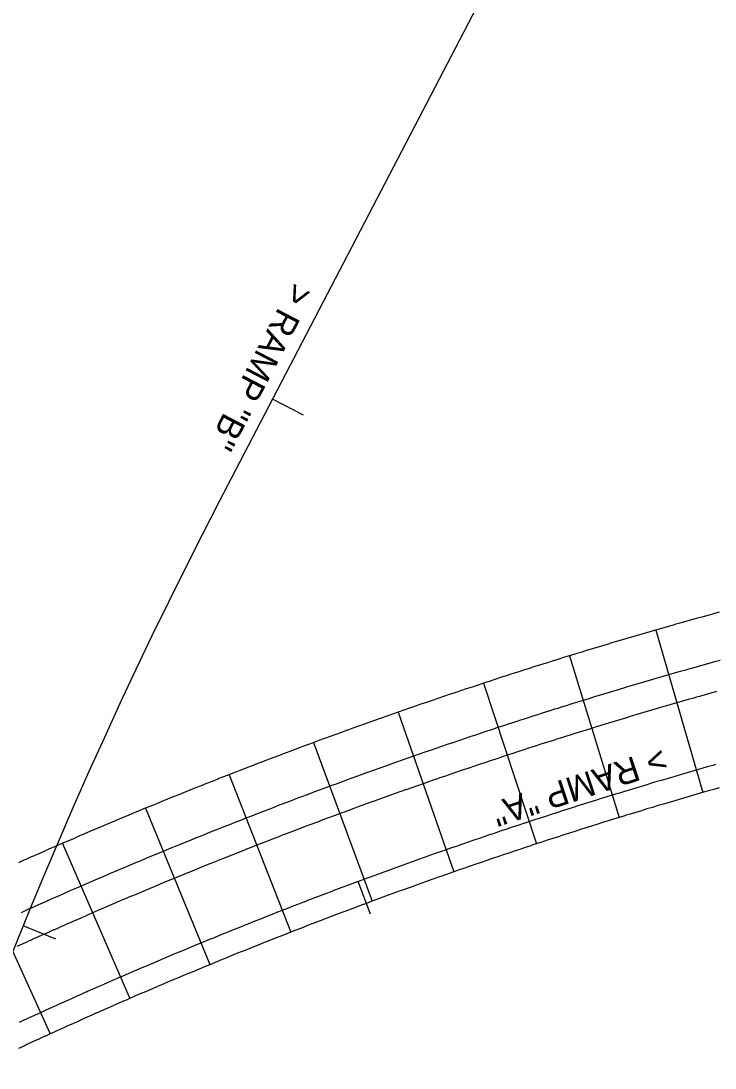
# Model space of a CAD drawing. Extents: x 2145147 to 2158018, y 137519 to 148068.
# Drawn here: x 2150298.8 to 2150417.8, y 143485.8 to 143665.3 of the extents above; entities that cross this region are included whole.
import ezdxf

# ---------------------------------------------------------------- set-up
doc = ezdxf.new("R2010")
doc.units = 0
for name, color, linetype in [('PR_Align_Ramp_A', 7, 'Continuous'), ('PR_Align_Ramp_A_Label', 7, 'Continuous'), ('PR_Align_Ramp_B', 7, 'Continuous'), ('PR_Align_Ramp_B_Label', 7, 'Continuous'), ('PR_Joint_Contraction', 7, 'Continuous'), ('PR_Joint_Long', 7, 'Continuous'), ('PR_Road_Concrete', 7, 'Continuous')]:
    doc.layers.add(name, color=color, linetype=linetype)

msp = doc.modelspace()

# ---------------------------------------------------------------- linework, layer by layer
at = {"layer": 'PR_Align_Ramp_A'}
msp.add_lwpolyline([(2150358.73, 143512.15), (2150356.64, 143517.77)], dxfattribs=at)
at = {"layer": 'PR_Align_Ramp_B'}
msp.add_line((2150377.59, 143669), (2150332.79, 143582.93), dxfattribs=at)
for points in [[(2150347.25, 143597.71), (2150341.93, 143600.48)], [(2150304.74, 143507.88), (2150299.18, 143510.14)]]:
    msp.add_lwpolyline(points, dxfattribs=at)
msp.add_arc((2151085.75, 143191.05), 848.83, 152.5051, 261.84091, dxfattribs=at)
at = {"layer": 'PR_Joint_Contraction'}
for p, q in [((2150407.66, 143560.88), (2150415.7, 143533.02)), ((2150392.85, 143556.46), (2150401.4, 143528.75)), ((2150378.12, 143551.77), (2150387.17, 143524.22)), ((2150363.48, 143546.81), (2150373.04, 143519.43)), ((2150348.93, 143541.58), (2150358.99, 143514.38)), ((2150334.48, 143536.08), (2150345.04, 143509.07)), ((2150320.14, 143530.33), (2150331.19, 143503.51)), ((2150305.9, 143524.31), (2150317.44, 143497.7)), ((2150291.78, 143518.03), (2150303.8, 143491.64))]:
    msp.add_line(p, q, dxfattribs=at)
at = {"layer": 'PR_Joint_Long'}
for points in [[(2150418.69, 143555.69), (2150417.72, 143555.42), (2150416.73, 143555.14), (2150415.74, 143554.86), (2150414.76, 143554.59), (2150413.78, 143554.31), (2150413.28, 143554.17), (2150412.8, 143554.03), (2150411.81, 143553.75), (2150410.83, 143553.47), (2150409.86, 143553.19), (2150408.87, 143552.91), (2150407.91, 143552.63), (2150407.67, 143552.56), (2150406.91, 143552.33), (2150405.93, 143552.05), (2150404.95, 143551.76), (2150403.98, 143551.47), (2150402.99, 143551.18), (2150402.31, 143550.97), (2150402.28, 143550.97), (2150401.04, 143550.59), (2150400.06, 143550.3), (2150399.09, 143550), (2150398.11, 143549.71), (2150397.13, 143549.41), (2150396.44, 143549.2), (2150396.15, 143549.11), (2150395.18, 143548.81), (2150394.21, 143548.51), (2150393.23, 143548.21), (2150392.26, 143547.9), (2150391.27, 143547.59), (2150390.84, 143547.46), (2150390.31, 143547.29), (2150389.33, 143546.98), (2150388.36, 143546.67), (2150387.39, 143546.36), (2150386.42, 143546.05), (2150385.42, 143545.73), (2150385.24, 143545.67), (2150384.47, 143545.43), (2150383.5, 143545.11), (2150382.53, 143544.8), (2150381.56, 143544.48), (2150380.59, 143544.16), (2150379.74, 143543.88), (2150379.66, 143543.85), (2150378.65, 143543.52), (2150377.68, 143543.2), (2150376.72, 143542.88), (2150375.75, 143542.55), (2150374.78, 143542.23), (2150374.14, 143542.01), (2150373.8, 143541.9), (2150372.85, 143541.57), (2150371.88, 143541.25), (2150370.91, 143540.91), (2150369.95, 143540.58), (2150368.98, 143540.25), (2150368.59, 143540.12), (2150368.03, 143539.92), (2150367.05, 143539.58), (2150366.09, 143539.25), (2150365.12, 143538.91), (2150364.17, 143538.57), (2150363.18, 143538.22), (2150363.04, 143538.17), (2150362.24, 143537.89), (2150361.28, 143537.55), (2150360.32, 143537.21), (2150359.36, 143536.86), (2150358.4, 143536.52), (2150357.53, 143536.2), (2150357.4, 143536.16), (2150356.48, 143535.82), (2150355.51, 143535.47), (2150354.56, 143535.12), (2150353.6, 143534.77), (2150352.65, 143534.42), (2150352.05, 143534.2), (2150351.66, 143534.06), (2150350.73, 143533.71), (2150349.77, 143533.36), (2150348.82, 143533), (2150347.86, 143532.64), (2150346.9, 143532.28), (2150346.57, 143532.16), (2150345.94, 143531.92), (2150345, 143531.56), (2150344.04, 143531.2), (2150343.08, 143530.83), (2150342.13, 143530.47), (2150341.29, 143530.14), (2150341.21, 143530.11), (2150340.22, 143529.73), (2150339.28, 143529.37), (2150338.32, 143528.99), (2150337.37, 143528.62), (2150336.42, 143528.25), (2150335.64, 143527.95), (2150335.45, 143527.87), (2150334.52, 143527.5), (2150333.57, 143527.13), (2150332.63, 143526.75), (2150331.67, 143526.37), (2150330.72, 143525.99), (2150330.23, 143525.79), (2150329.79, 143525.62), (2150328.83, 143525.23), (2150327.89, 143524.85), (2150326.94, 143524.47), (2150325.99, 143524.08), (2150325.06, 143523.7), (2150324.79, 143523.59), (2150324.1, 143523.3), (2150323.16, 143522.92), (2150322.22, 143522.53), (2150321.28, 143522.14), (2150320.33, 143521.75), (2150319.22, 143521.28), (2150319.2, 143521.28), (2150318.45, 143520.96), (2150317.51, 143520.56), (2150316.57, 143520.17), (2150315.63, 143519.77), (2150314.68, 143519.37), (2150313.99, 143519.08), (2150313.75, 143518.97), (2150312.81, 143518.57), (2150311.87, 143518.17), (2150310.94, 143517.77), (2150310, 143517.36), (2150309.25, 143517.04), (2150309.05, 143516.95), (2150308.6, 143516.76), (2150308.14, 143516.56), (2150307.72, 143516.37), (2150307.18, 143516.14), (2150306.28, 143515.74), (2150306.19, 143515.71), (2150305.32, 143515.32), (2150304.66, 143515.03), (2150304.37, 143514.9), (2150303.47, 143514.51), (2150303.25, 143514.41), (2150303.12, 143514.35), (2150302.48, 143514.07), (2150302.38, 143514.02), (2150301.6, 143513.68), (2150301.56, 143513.66), (2150300.65, 143513.26), (2150300.1, 143513.01), (2150299.72, 143512.84), (2150298.8, 143512.42)], [(2150418.07, 143550.33), (2150417.09, 143550.05), (2150416.12, 143549.78), (2150415.15, 143549.5), (2150414.64, 143549.36), (2150414.16, 143549.22), (2150413.19, 143548.95), (2150412.21, 143548.67), (2150411.24, 143548.39), (2150410.26, 143548.1), (2150409.3, 143547.82), (2150409.06, 143547.75), (2150408.31, 143547.54), (2150407.34, 143547.25), (2150406.37, 143546.96), (2150405.4, 143546.68), (2150404.42, 143546.39), (2150403.66, 143546.16), (2150403.63, 143546.15), (2150402.48, 143545.8), (2150401.51, 143545.51), (2150400.54, 143545.22), (2150399.57, 143544.93), (2150398.59, 143544.63), (2150397.9, 143544.42), (2150397.62, 143544.33), (2150396.65, 143544.03), (2150395.69, 143543.73), (2150394.72, 143543.43), (2150393.75, 143543.13), (2150392.77, 143542.82), (2150392.34, 143542.69), (2150391.81, 143542.52), (2150390.84, 143542.21), (2150389.88, 143541.91), (2150388.91, 143541.6), (2150387.95, 143541.29), (2150386.96, 143540.98), (2150386.78, 143540.92), (2150386.01, 143540.67), (2150385.04, 143540.36), (2150384.08, 143540.04), (2150383.12, 143539.73), (2150382.15, 143539.41), (2150381.29, 143539.13), (2150381.22, 143539.1), (2150380.22, 143538.77), (2150379.26, 143538.45), (2150378.31, 143538.14), (2150377.34, 143537.81), (2150376.38, 143537.49), (2150375.74, 143537.27), (2150375.41, 143537.16), (2150374.46, 143536.84), (2150373.5, 143536.51), (2150372.53, 143536.18), (2150371.57, 143535.85), (2150370.61, 143535.52), (2150370.23, 143535.39), (2150369.66, 143535.19), (2150368.7, 143534.86), (2150367.74, 143534.53), (2150366.78, 143534.19), (2150365.82, 143533.85), (2150364.85, 143533.51), (2150364.72, 143533.46), (2150363.91, 143533.18), (2150362.95, 143532.84), (2150362, 143532.5), (2150361.05, 143532.16), (2150360.09, 143531.81), (2150359.24, 143531.51), (2150359.11, 143531.46), (2150358.18, 143531.12), (2150357.22, 143530.78), (2150356.27, 143530.43), (2150355.32, 143530.08), (2150354.37, 143529.73), (2150353.79, 143529.52), (2150353.4, 143529.37), (2150352.47, 143529.02), (2150351.52, 143528.67), (2150350.57, 143528.32), (2150349.61, 143527.96), (2150348.66, 143527.6), (2150348.34, 143527.48), (2150347.71, 143527.24), (2150346.77, 143526.89), (2150345.82, 143526.52), (2150344.87, 143526.16), (2150343.92, 143525.8), (2150343.06, 143525.47), (2150342.98, 143525.44), (2150342.02, 143525.07), (2150341.09, 143524.7), (2150340.14, 143524.34), (2150339.19, 143523.97), (2150338.25, 143523.6), (2150337.48, 143523.3), (2150337.29, 143523.22), (2150336.36, 143522.85), (2150335.42, 143522.48), (2150334.48, 143522.11), (2150333.53, 143521.73), (2150332.58, 143521.35), (2150332.09, 143521.15), (2150331.65, 143520.98), (2150330.7, 143520.6), (2150329.76, 143520.22), (2150328.82, 143519.83), (2150327.88, 143519.45), (2150326.95, 143519.07), (2150326.69, 143518.96), (2150326, 143518.68), (2150325.07, 143518.3), (2150324.13, 143517.91), (2150323.19, 143517.52), (2150322.25, 143517.13), (2150321.2, 143516.69), (2150321.18, 143516.68), (2150320.38, 143516.35), (2150319.45, 143515.96), (2150318.52, 143515.56), (2150317.58, 143515.17), (2150316.64, 143514.77), (2150315.95, 143514.48), (2150315.71, 143514.37), (2150314.77, 143513.97), (2150313.85, 143513.57), (2150312.91, 143513.17), (2150311.98, 143512.77), (2150311.23, 143512.45), (2150311.04, 143512.37), (2150310.6, 143512.17), (2150310.13, 143511.97), (2150309.71, 143511.79), (2150309.19, 143511.56), (2150308.28, 143511.16), (2150308.2, 143511.13), (2150307.33, 143510.75), (2150306.67, 143510.46), (2150306.39, 143510.33), (2150305.49, 143509.93), (2150305.28, 143509.84), (2150305.15, 143509.78), (2150304.52, 143509.5), (2150304.42, 143509.46), (2150303.64, 143509.11), (2150303.6, 143509.09), (2150302.69, 143508.69), (2150302.14, 143508.44), (2150301.76, 143508.27), (2150300.85, 143507.86)], [(2150417.92, 143537.82), (2150417.45, 143537.68), (2150416.49, 143537.41), (2150415.53, 143537.13), (2150414.57, 143536.86), (2150413.6, 143536.58), (2150412.65, 143536.3), (2150412.41, 143536.23), (2150411.69, 143536.02), (2150410.72, 143535.74), (2150409.77, 143535.45), (2150408.81, 143535.17), (2150407.85, 143534.89), (2150406.91, 143534.61), (2150406.89, 143534.6), (2150405.93, 143534.31), (2150404.97, 143534.02), (2150404.02, 143533.73), (2150403.06, 143533.44), (2150402.1, 143533.15), (2150401.42, 143532.94), (2150401.15, 143532.86), (2150400.19, 143532.57), (2150399.24, 143532.27), (2150398.28, 143531.97), (2150397.33, 143531.68), (2150396.37, 143531.38), (2150395.94, 143531.24), (2150395.42, 143531.08), (2150394.47, 143530.77), (2150393.51, 143530.47), (2150392.56, 143530.17), (2150391.61, 143529.86), (2150390.66, 143529.56), (2150390.48, 143529.5), (2150389.7, 143529.25), (2150388.75, 143528.94), (2150387.8, 143528.63), (2150386.85, 143528.32), (2150385.9, 143528.01), (2150385.02, 143527.72), (2150384.95, 143527.7), (2150384, 143527.38), (2150383.05, 143527.07), (2150382.1, 143526.75), (2150381.16, 143526.44), (2150380.21, 143526.12), (2150379.58, 143525.91), (2150379.26, 143525.8), (2150378.31, 143525.48), (2150377.37, 143525.15), (2150376.42, 143524.83), (2150375.47, 143524.51), (2150374.53, 143524.18), (2150374.16, 143524.05), (2150373.58, 143523.85), (2150372.64, 143523.53), (2150371.69, 143523.2), (2150370.75, 143522.87), (2150369.81, 143522.54), (2150368.86, 143522.2), (2150368.74, 143522.16), (2150367.92, 143521.87), (2150366.98, 143521.53), (2150366.04, 143521.2), (2150365.1, 143520.86), (2150364.15, 143520.52), (2150363.34, 143520.23), (2150363.21, 143520.18), (2150362.27, 143519.84), (2150361.33, 143519.5), (2150360.4, 143519.16), (2150359.46, 143518.81), (2150358.52, 143518.47), (2150357.96, 143518.26), (2150357.58, 143518.12), (2150356.64, 143517.77), (2150355.71, 143517.43), (2150354.77, 143517.08), (2150353.83, 143516.73), (2150352.9, 143516.37), (2150352.58, 143516.26), (2150351.96, 143516.02), (2150351.02, 143515.67), (2150350.09, 143515.31), (2150349.16, 143514.95), (2150348.22, 143514.6), (2150347.29, 143514.24), (2150347.22, 143514.21), (2150346.36, 143513.88), (2150345.42, 143513.52), (2150344.49, 143513.15), (2150343.56, 143512.79), (2150342.63, 143512.43), (2150341.88, 143512.13), (2150341.7, 143512.06), (2150340.77, 143511.69), (2150339.84, 143511.32), (2150338.91, 143510.96), (2150337.98, 143510.59), (2150337.05, 143510.21), (2150336.55, 143510.01), (2150336.12, 143509.84), (2150335.19, 143509.47), (2150334.27, 143509.09), (2150333.34, 143508.72), (2150332.42, 143508.34), (2150331.49, 143507.96), (2150331.23, 143507.86), (2150330.56, 143507.58), (2150329.64, 143507.2), (2150328.71, 143506.82), (2150327.79, 143506.44), (2150326.87, 143506.05), (2150325.94, 143505.67), (2150325.94, 143505.66), (2150325.02, 143505.28), (2150324.1, 143504.89), (2150323.18, 143504.51), (2150322.26, 143504.12), (2150321.34, 143503.73), (2150320.65, 143503.43), (2150320.42, 143503.33), (2150319.5, 143502.94), (2150318.58, 143502.55), (2150317.66, 143502.15), (2150316.74, 143501.76), (2150315.99, 143501.43), (2150315.82, 143501.36), (2150315.38, 143501.17), (2150314.91, 143500.96), (2150314.5, 143500.78), (2150313.99, 143500.56), (2150313.07, 143500.16), (2150313, 143500.13), (2150312.16, 143499.76), (2150311.51, 143499.47), (2150311.24, 143499.36), (2150310.33, 143498.95), (2150310.13, 143498.86), (2150310.02, 143498.82), (2150309.41, 143498.55), (2150309.32, 143498.51), (2150308.53, 143498.15), (2150308.5, 143498.14), (2150307.59, 143497.73), (2150307.04, 143497.49), (2150306.67, 143497.32), (2150305.76, 143496.91)], [(2150300.82, 143507.85), (2150300.62, 143507.76), (2150299.95, 143507.46), (2150299.9, 143507.43), (2150299.12, 143507.08), (2150298.98, 143507.02), (2150298.07, 143506.61)], [(2150305.76, 143496.91), (2150305.55, 143496.82), (2150304.9, 143496.52), (2150304.85, 143496.5), (2150304.07, 143496.15), (2150303.94, 143496.09), (2150303.03, 143495.68), (2150302.58, 143495.48), (2150302.12, 143495.27), (2150301.21, 143494.85), (2150301.1, 143494.8), (2150300.3, 143494.43), (2150299.68, 143494.15), (2150299.62, 143494.12), (2150299.39, 143494.02), (2150298.48, 143493.6)]]:
    msp.add_lwpolyline(points, dxfattribs=at)
at = {"layer": 'PR_Road_Concrete'}
for points in [[(2150418.55, 143563.95), (2150417.55, 143563.67), (2150416.78, 143563.46), (2150416.56, 143563.4), (2150415.57, 143563.12), (2150414.57, 143562.85), (2150413.58, 143562.57), (2150412.59, 143562.29), (2150411.6, 143562.01), (2150411.09, 143561.87), (2150410.61, 143561.73), (2150409.62, 143561.44), (2150408.62, 143561.16), (2150407.63, 143560.88), (2150406.64, 143560.59), (2150405.65, 143560.3), (2150405.41, 143560.23), (2150404.67, 143560.01), (2150403.68, 143559.72), (2150402.69, 143559.43), (2150401.7, 143559.14), (2150400.71, 143558.85), (2150399.74, 143558.56), (2150399.72, 143558.55), (2150398.74, 143558.26), (2150397.75, 143557.96), (2150396.76, 143557.66), (2150395.78, 143557.36), (2150394.79, 143557.06), (2150394.09, 143556.84), (2150393.81, 143556.76), (2150392.82, 143556.45), (2150391.84, 143556.15), (2150390.85, 143555.84), (2150389.87, 143555.54), (2150388.89, 143555.23), (2150388.44, 143555.09), (2150387.9, 143554.92), (2150386.92, 143554.61), (2150385.94, 143554.3), (2150384.96, 143553.98), (2150383.97, 143553.67), (2150382.99, 143553.35), (2150382.81, 143553.3), (2150382.01, 143553.04), (2150381.03, 143552.72), (2150380.05, 143552.4), (2150379.07, 143552.08), (2150378.09, 143551.76), (2150377.19, 143551.46), (2150377.12, 143551.44), (2150376.14, 143551.11), (2150375.16, 143550.79), (2150374.18, 143550.46), (2150373.2, 143550.14), (2150372.23, 143549.81), (2150371.58, 143549.59), (2150371.25, 143549.48), (2150370.27, 143549.15), (2150369.3, 143548.82), (2150368.32, 143548.48), (2150367.35, 143548.15), (2150366.37, 143547.81), (2150365.99, 143547.68), (2150365.4, 143547.48), (2150364.43, 143547.14), (2150363.45, 143546.8), (2150362.48, 143546.46), (2150361.51, 143546.12), (2150360.54, 143545.77), (2150360.41, 143545.73), (2150359.56, 143545.43), (2150358.59, 143545.09), (2150357.62, 143544.74), (2150356.65, 143544.39), (2150355.68, 143544.04), (2150354.85, 143543.74), (2150354.71, 143543.69), (2150353.74, 143543.34), (2150352.78, 143542.99), (2150351.81, 143542.64), (2150350.84, 143542.28), (2150349.87, 143541.93), (2150349.29, 143541.71), (2150348.91, 143541.57), (2150347.94, 143541.21), (2150346.97, 143540.85), (2150346.01, 143540.49), (2150345.04, 143540.13), (2150344.08, 143539.77), (2150343.76, 143539.65), (2150343.12, 143539.4), (2150342.15, 143539.04), (2150341.19, 143538.67), (2150340.23, 143538.3), (2150339.26, 143537.94), (2150338.3, 143537.57), (2150338.24, 143537.54), (2150337.34, 143537.19), (2150336.38, 143536.82), (2150335.42, 143536.45), (2150334.46, 143536.07), (2150333.5, 143535.7), (2150332.73, 143535.4), (2150332.54, 143535.32), (2150331.58, 143534.94), (2150330.62, 143534.57), (2150329.67, 143534.18), (2150328.71, 143533.8), (2150327.75, 143533.42), (2150327.23, 143533.21), (2150326.79, 143533.04), (2150325.84, 143532.65), (2150324.88, 143532.27), (2150323.93, 143531.88), (2150322.97, 143531.49), (2150322.02, 143531.1), (2150321.76, 143530.99), (2150321.07, 143530.71), (2150320.11, 143530.32), (2150319.16, 143529.92), (2150318.21, 143529.53), (2150317.26, 143529.13), (2150316.31, 143528.74), (2150316.3, 143528.73), (2150315.36, 143528.34), (2150314.4, 143527.94), (2150313.46, 143527.54), (2150312.51, 143527.14), (2150311.56, 143526.73), (2150310.85, 143526.43), (2150310.61, 143526.33), (2150309.66, 143525.93), (2150308.71, 143525.52), (2150307.77, 143525.11), (2150306.82, 143524.7), (2150306.05, 143524.37), (2150305.88, 143524.3), (2150305.42, 143524.1), (2150304.93, 143523.88), (2150304.51, 143523.7), (2150303.99, 143523.47), (2150303.04, 143523.06), (2150302.97, 143523.03), (2150302.1, 143522.65), (2150301.43, 143522.35), (2150301.15, 143522.23), (2150300.21, 143521.81), (2150300.01, 143521.72), (2150299.9, 143521.67), (2150299.27, 143521.4), (2150299.18, 143521.35), (2150298.36, 143520.99)], [(2150418.54, 143533.84), (2150417.59, 143533.56), (2150416.63, 143533.29), (2150415.67, 143533.01), (2150414.72, 143532.74), (2150413.76, 143532.46), (2150413.53, 143532.39), (2150412.81, 143532.18), (2150411.85, 143531.9), (2150410.9, 143531.62), (2150409.94, 143531.34), (2150408.99, 143531.05), (2150408.05, 143530.77), (2150408.04, 143530.77), (2150407.08, 143530.48), (2150406.13, 143530.2), (2150405.18, 143529.91), (2150404.23, 143529.62), (2150403.27, 143529.33), (2150402.59, 143529.12), (2150402.32, 143529.04), (2150401.37, 143528.74), (2150400.42, 143528.45), (2150399.47, 143528.15), (2150398.52, 143527.86), (2150397.57, 143527.56), (2150397.14, 143527.43), (2150396.62, 143527.26), (2150395.67, 143526.96), (2150394.72, 143526.66), (2150393.78, 143526.36), (2150392.83, 143526.06), (2150391.88, 143525.75), (2150391.71, 143525.69), (2150390.94, 143525.45), (2150389.99, 143525.14), (2150389.04, 143524.83), (2150388.1, 143524.52), (2150387.15, 143524.21), (2150386.28, 143523.92), (2150386.21, 143523.9), (2150385.26, 143523.59), (2150384.32, 143523.27), (2150383.37, 143522.96), (2150382.43, 143522.64), (2150381.48, 143522.33), (2150380.87, 143522.12), (2150380.54, 143522.01), (2150379.6, 143521.69), (2150378.66, 143521.37), (2150377.72, 143521.05), (2150376.77, 143520.72), (2150375.83, 143520.4), (2150375.46, 143520.27), (2150374.89, 143520.07), (2150373.95, 143519.75), (2150373.01, 143519.42), (2150372.07, 143519.09), (2150371.13, 143518.76), (2150370.2, 143518.43), (2150370.08, 143518.39), (2150369.26, 143518.1), (2150368.32, 143517.77), (2150367.38, 143517.43), (2150366.45, 143517.1), (2150365.51, 143516.76), (2150364.7, 143516.47), (2150364.57, 143516.42), (2150363.64, 143516.08), (2150362.7, 143515.74), (2150361.77, 143515.4), (2150360.83, 143515.06), (2150359.9, 143514.71), (2150359.34, 143514.51), (2150358.97, 143514.37), (2150358.03, 143514.02), (2150357.1, 143513.68), (2150356.17, 143513.33), (2150355.24, 143512.98), (2150354.31, 143512.63), (2150353.99, 143512.51), (2150353.38, 143512.28), (2150352.44, 143511.93), (2150351.51, 143511.57), (2150350.58, 143511.22), (2150349.65, 143510.86), (2150348.73, 143510.51), (2150348.66, 143510.48), (2150347.8, 143510.15), (2150346.87, 143509.79), (2150345.94, 143509.43), (2150345.02, 143509.07), (2150344.09, 143508.7), (2150343.34, 143508.41), (2150343.16, 143508.34), (2150342.24, 143507.97), (2150341.31, 143507.61), (2150340.39, 143507.24), (2150339.46, 143506.87), (2150338.54, 143506.5), (2150338.04, 143506.3), (2150337.62, 143506.13), (2150336.69, 143505.76), (2150335.77, 143505.39), (2150334.85, 143505.01), (2150333.93, 143504.64), (2150333, 143504.26), (2150332.75, 143504.16), (2150332.08, 143503.88), (2150331.16, 143503.5), (2150330.24, 143503.12), (2150329.32, 143502.74), (2150328.41, 143502.36), (2150327.49, 143501.98), (2150327.48, 143501.97), (2150326.57, 143501.59), (2150325.65, 143501.21), (2150324.73, 143500.82), (2150323.82, 143500.43), (2150322.9, 143500.05), (2150322.22, 143499.76), (2150321.99, 143499.66), (2150321.07, 143499.27), (2150320.16, 143498.87), (2150319.24, 143498.48), (2150318.33, 143498.08), (2150317.59, 143497.76), (2150317.42, 143497.69), (2150316.98, 143497.5), (2150316.5, 143497.29), (2150316.1, 143497.12), (2150315.59, 143496.9), (2150314.68, 143496.5), (2150314.61, 143496.47), (2150313.77, 143496.1), (2150313.12, 143495.81), (2150312.86, 143495.7), (2150311.95, 143495.29), (2150311.75, 143495.21), (2150311.64, 143495.16), (2150311.04, 143494.89), (2150310.95, 143494.85), (2150310.16, 143494.5), (2150310.13, 143494.49), (2150309.22, 143494.08), (2150308.68, 143493.84), (2150308.31, 143493.67), (2150307.4, 143493.27)], [(2150307.4, 143493.27), (2150307.2, 143493.17), (2150306.54, 143492.88), (2150306.5, 143492.86), (2150305.72, 143492.51), (2150305.59, 143492.45), (2150304.68, 143492.04), (2150304.24, 143491.83), (2150303.78, 143491.62), (2150302.87, 143491.21), (2150302.76, 143491.16), (2150301.97, 143490.8), (2150301.35, 143490.51), (2150301.29, 143490.49), (2150301.06, 143490.38), (2150300.16, 143489.97), (2150299.81, 143489.81), (2150299.26, 143489.55), (2150298.35, 143489.13)]]:
    msp.add_lwpolyline(points, dxfattribs=at)

# ---------------------------------------------------------------- texts
at = {"layer": 'PR_Align_Ramp_A_Label'}
msp.add_text('> RAMP "A"', height=4.3, rotation=198.1968, dxfattribs=at).set_placement((2150408.68, 143540.89))
at = {"layer": 'PR_Align_Ramp_B_Label'}
msp.add_text('> RAMP "B"', height=4.3, rotation=242.4776, dxfattribs=at).set_placement((2150345.29, 143620.74))

doc.saveas('drawing.dxf')
